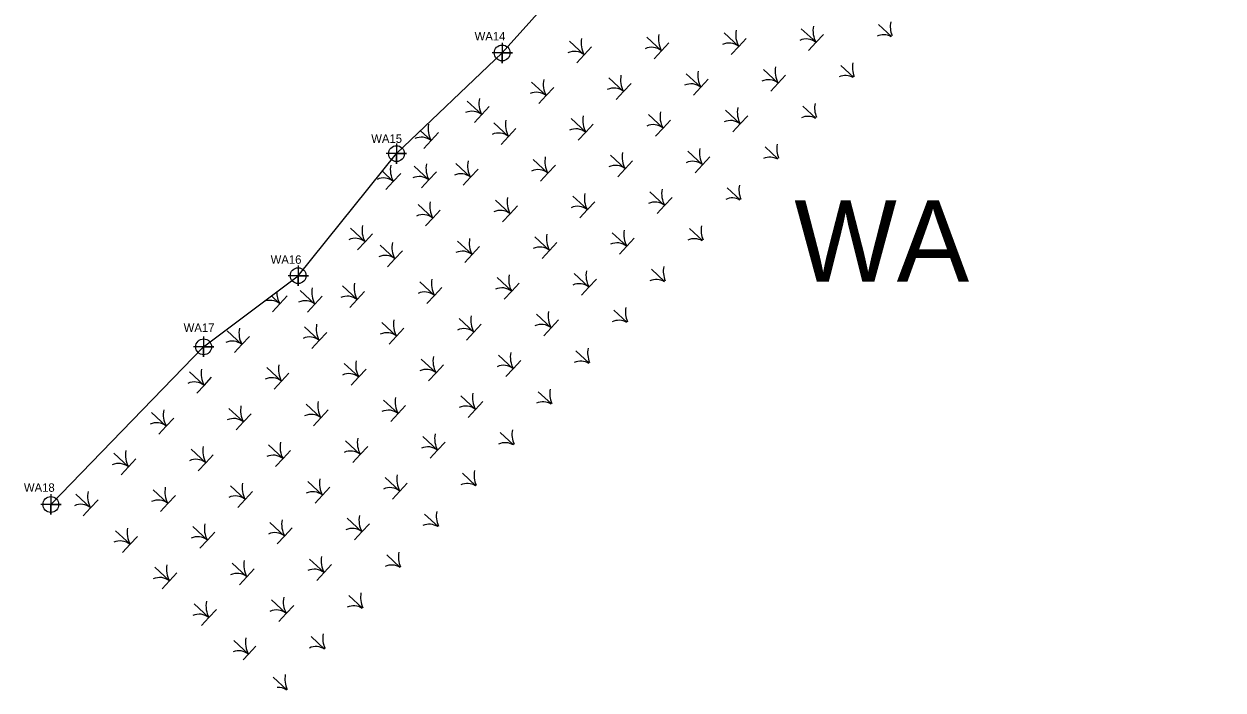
# Model space of a CAD drawing. Extents: x 2130226 to 2130625, y 149525 to 150037.
# Drawn here: x 2130259.3 to 2130613.9, y 149524.5 to 149721.4 of the extents above; entities that cross this region are included whole.
import ezdxf

# ---------------------------------------------------------------- set-up
doc = ezdxf.new("R2010")
doc.units = 0
for name, color, linetype in [('Default', 7, 'Continuous'), ('Exist Environmental Wetland Boundary', 7, 'Continuous'), ('Exist Environmental Wetland Boundary Cogo Number', 7, 'Continuous'), ('Exist Environmental Wetland Boundary Cogo Point CELL', 7, 'Continuous')]:
    doc.layers.add(name, color=color, linetype=linetype)

msp = doc.modelspace()

# ---------------------------------------------------------------- linework, layer by layer
at = {"layer": 'Exist Environmental Wetland Boundary'}
msp.add_lwpolyline([(2130267.29, 149579.38), (2130312.46, 149626), (2130340.44, 149647.02), (2130369.49, 149683.11), (2130400.77, 149712.88), (2130426.19, 149741.24), (2130464.98, 149782.24), (2130485.26, 149806.46), (2130501.4, 149821.48), (2130516.1, 149818.66), (2130536.83, 149803.31), (2130542.55, 149811.9), (2130506.33, 149839.82), (2130501.18, 149853.93), (2130523.76, 149857.7), (2130544.93, 149871.63), (2130588.13, 149840.59), (2130613.94, 149823.8)], dxfattribs=at)
at = {"layer": 'Exist Environmental Wetland Boundary Cogo Point CELL'}
for points in [[(2130515.85, 149717.78), (2130512.09, 149721.26), (2130515.85, 149717.78)], [(2130445.66, 149711.18), (2130447.85, 149713.54), (2130443.51, 149717.57), (2130447.85, 149713.54), (2130450.05, 149715.91)], [(2130468.52, 149712.41), (2130470.71, 149714.77), (2130466.37, 149718.8), (2130470.71, 149714.77), (2130472.9, 149717.14)], [(2130491.37, 149713.64), (2130493.57, 149716.01), (2130489.23, 149720.03), (2130493.57, 149716.01), (2130495.76, 149718.37)], [(2130400.77, 149715.88), (2130400.77, 149709.88), (2130400.77, 149712.88), (2130403.77, 149712.88), (2130397.77, 149712.88)], [(2130422.8, 149709.94), (2130424.99, 149712.31), (2130420.66, 149716.33), (2130424.99, 149712.31), (2130427.19, 149714.67)], [(2130457.33, 149700.35), (2130459.52, 149702.71), (2130455.18, 149706.74), (2130459.52, 149702.71), (2130461.71, 149705.08)], [(2130480.18, 149701.58), (2130482.38, 149703.95), (2130478.04, 149707.97), (2130482.38, 149703.95), (2130484.57, 149706.31)], [(2130504.67, 149705.7), (2130500.9, 149709.2), (2130504.67, 149705.7)], [(2130411.61, 149697.88), (2130413.8, 149700.25), (2130409.47, 149704.27), (2130413.8, 149700.25), (2130416, 149702.61)], [(2130434.47, 149699.12), (2130436.66, 149701.48), (2130432.32, 149705.51), (2130436.66, 149701.48), (2130438.86, 149703.85)], [(2130392.57, 149692.26), (2130394.77, 149694.63), (2130390.43, 149698.65), (2130394.77, 149694.63), (2130396.96, 149696.99)], [(2130468.99, 149689.52), (2130471.19, 149691.89), (2130466.85, 149695.91), (2130471.19, 149691.89), (2130473.38, 149694.25)], [(2130493.5, 149693.63), (2130489.71, 149697.14), (2130493.5, 149693.63)], [(2130400.42, 149685.83), (2130402.61, 149688.19), (2130398.28, 149692.22), (2130402.61, 149688.19), (2130404.81, 149690.55)], [(2130423.28, 149687.06), (2130425.47, 149689.42), (2130421.13, 149693.45), (2130425.47, 149689.42), (2130427.67, 149691.79)], [(2130446.14, 149688.29), (2130448.33, 149690.65), (2130443.99, 149694.68), (2130448.33, 149690.65), (2130450.52, 149693.02)], [(2130377.56, 149684.59), (2130379.76, 149686.96), (2130376.61, 149689.88)], [(2130376.61, 149689.88), (2130379.76, 149686.96), (2130381.95, 149689.32)], [(2130369.49, 149686.11), (2130369.49, 149680.11), (2130369.49, 149683.11), (2130372.49, 149683.11), (2130366.49, 149683.11)], [(2130482.33, 149681.55), (2130478.52, 149685.08), (2130482.33, 149681.55)], [(2130412.09, 149675), (2130414.28, 149677.36), (2130409.94, 149681.39), (2130414.28, 149677.36), (2130416.48, 149679.73)], [(2130434.95, 149676.23), (2130437.14, 149678.6), (2130432.8, 149682.62), (2130437.14, 149678.6), (2130439.33, 149680.96)], [(2130457.8, 149677.46), (2130460, 149679.83), (2130455.66, 149683.85), (2130460, 149679.83), (2130462.19, 149682.19)], [(2130366.37, 149672.53), (2130368.57, 149674.9), (2130365.32, 149677.91)], [(2130365.32, 149677.91), (2130368.57, 149674.9), (2130370.76, 149677.26)], [(2130376.92, 149672.96), (2130379.11, 149675.32), (2130374.78, 149679.35), (2130379.11, 149675.32), (2130381.31, 149677.69)], [(2130389.23, 149673.77), (2130391.42, 149676.13), (2130387.09, 149680.16), (2130391.42, 149676.13), (2130393.62, 149678.5)], [(2130423.76, 149664.17), (2130425.95, 149666.54), (2130421.61, 149670.56), (2130425.95, 149666.54), (2130428.14, 149668.9)], [(2130446.61, 149665.4), (2130448.81, 149667.77), (2130444.47, 149671.79), (2130448.81, 149667.77), (2130451, 149670.13)], [(2130471.16, 149669.47), (2130467.33, 149673.03), (2130471.16, 149669.47)], [(2130378.04, 149661.71), (2130380.23, 149664.07), (2130375.9, 149668.1), (2130380.23, 149664.07), (2130382.43, 149666.44)], [(2130400.9, 149662.94), (2130403.09, 149665.3), (2130398.75, 149669.33), (2130403.09, 149665.3), (2130405.29, 149667.67)], [(2130358.01, 149654.71), (2130360.2, 149657.07), (2130355.87, 149661.1), (2130360.2, 149657.07), (2130362.4, 149659.44)], [(2130459.98, 149657.4), (2130456.14, 149660.97), (2130459.98, 149657.4)], [(2130389.71, 149650.88), (2130391.9, 149653.24), (2130387.56, 149657.27), (2130391.9, 149653.24), (2130394.1, 149655.61)], [(2130412.57, 149652.11), (2130414.76, 149654.48), (2130410.42, 149658.5), (2130414.76, 149654.48), (2130416.95, 149656.84)], [(2130435.42, 149653.34), (2130437.62, 149655.71), (2130433.28, 149659.73), (2130437.62, 149655.71), (2130439.81, 149658.07)], [(2130366.85, 149649.65), (2130369.04, 149652.01), (2130364.71, 149656.04), (2130369.04, 149652.01), (2130371.24, 149654.38)], [(2130340.44, 149650.02), (2130340.44, 149644.02), (2130340.44, 149647.02), (2130343.44, 149647.02), (2130337.44, 149647.02)], [(2130401.38, 149640.05), (2130403.57, 149642.42), (2130399.23, 149646.44), (2130403.57, 149642.42), (2130405.76, 149644.78)], [(2130424.23, 149641.28), (2130426.43, 149643.65), (2130422.09, 149647.67), (2130426.43, 149643.65), (2130428.62, 149646.01)], [(2130448.81, 149645.32), (2130444.95, 149648.91), (2130448.81, 149645.32)], [(2130343.18, 149636.25), (2130345.37, 149638.61), (2130341.03, 149642.64), (2130345.37, 149638.61), (2130347.56, 149640.98)], [(2130355.66, 149637.59), (2130357.85, 149639.95), (2130353.52, 149643.98), (2130357.85, 149639.95), (2130360.05, 149642.32)], [(2130378.52, 149638.82), (2130380.71, 149641.19), (2130376.37, 149645.21), (2130380.71, 149641.19), (2130382.91, 149643.55)], [(2130332.49, 149641.04), (2130335, 149638.72), (2130337.19, 149641.09)], [(2130332.8, 149636.36), (2130335, 149638.72), (2130332.49, 149641.04)], [(2130413.04, 149629.23), (2130415.24, 149631.59), (2130410.9, 149635.62), (2130415.24, 149631.59), (2130417.43, 149633.95)], [(2130437.64, 149633.25), (2130433.76, 149636.85), (2130437.64, 149633.25)], [(2130344.47, 149625.53), (2130346.66, 149627.89), (2130342.33, 149631.92), (2130346.66, 149627.89), (2130348.86, 149630.26)], [(2130367.33, 149626.76), (2130369.52, 149629.13), (2130365.18, 149633.15), (2130369.52, 149629.13), (2130371.72, 149631.49)], [(2130390.19, 149627.99), (2130392.38, 149630.36), (2130388.04, 149634.38), (2130392.38, 149630.36), (2130394.57, 149632.72)], [(2130312.46, 149629), (2130312.46, 149623), (2130312.46, 149626), (2130315.46, 149626), (2130309.46, 149626)], [(2130321.61, 149624.3), (2130323.81, 149626.66), (2130319.47, 149630.69), (2130323.81, 149626.66), (2130326, 149629.03)], [(2130426.47, 149621.17), (2130422.57, 149624.79), (2130426.47, 149621.17)], [(2130356.14, 149614.7), (2130358.33, 149617.07), (2130353.99, 149621.09), (2130358.33, 149617.07), (2130360.53, 149619.43)], [(2130379, 149615.93), (2130381.19, 149618.3), (2130376.85, 149622.32), (2130381.19, 149618.3), (2130383.38, 149620.66)], [(2130401.85, 149617.17), (2130404.05, 149619.53), (2130399.71, 149623.56), (2130404.05, 149619.53), (2130406.24, 149621.9)], [(2130310.42, 149612.24), (2130312.62, 149614.6), (2130308.28, 149618.63), (2130312.62, 149614.6), (2130314.81, 149616.97)], [(2130333.28, 149613.47), (2130335.47, 149615.83), (2130331.14, 149619.86), (2130335.47, 149615.83), (2130337.67, 149618.2)], [(2130367.81, 149603.87), (2130370, 149606.24), (2130365.66, 149610.26), (2130370, 149606.24), (2130372.19, 149608.6)], [(2130390.66, 149605.11), (2130392.86, 149607.47), (2130388.52, 149611.5), (2130392.86, 149607.47), (2130395.05, 149609.84)], [(2130415.3, 149609.09), (2130411.38, 149612.73), (2130415.3, 149609.09)], [(2130322.09, 149601.41), (2130324.28, 149603.77), (2130319.95, 149607.8), (2130324.28, 149603.77), (2130326.48, 149606.14)], [(2130344.95, 149602.64), (2130347.14, 149605.01), (2130342.8, 149609.03), (2130347.14, 149605.01), (2130349.34, 149607.37)], [(2130299.23, 149600.18), (2130301.43, 149602.54), (2130297.09, 149606.57), (2130301.43, 149602.54), (2130303.62, 149604.91)], [(2130404.12, 149597.02), (2130400.19, 149600.67), (2130404.12, 149597.02)], [(2130333.76, 149590.58), (2130335.95, 149592.95), (2130331.61, 149596.97), (2130335.95, 149592.95), (2130338.15, 149595.31)], [(2130356.62, 149591.82), (2130358.81, 149594.18), (2130354.47, 149598.21), (2130358.81, 149594.18), (2130361, 149596.54)], [(2130379.47, 149593.05), (2130381.67, 149595.41), (2130377.33, 149599.44), (2130381.67, 149595.41), (2130383.86, 149597.78)], [(2130288.04, 149588.12), (2130290.24, 149590.48), (2130285.9, 149594.51), (2130290.24, 149590.48), (2130292.43, 149592.85)], [(2130310.9, 149589.35), (2130313.09, 149591.72), (2130308.76, 149595.74), (2130313.09, 149591.72), (2130315.29, 149594.08)], [(2130345.43, 149579.76), (2130347.62, 149582.12), (2130343.28, 149586.15), (2130347.62, 149582.12), (2130349.81, 149584.49)], [(2130368.28, 149580.99), (2130370.48, 149583.35), (2130366.14, 149587.38), (2130370.48, 149583.35), (2130372.67, 149585.72)], [(2130392.95, 149584.94), (2130389, 149588.61), (2130392.95, 149584.94)], [(2130267.29, 149582.38), (2130267.29, 149576.38), (2130267.29, 149579.38), (2130270.29, 149579.38), (2130264.29, 149579.38)], [(2130276.85, 149576.06), (2130279.05, 149578.42), (2130274.71, 149582.45), (2130279.05, 149578.42), (2130281.24, 149580.79)], [(2130299.71, 149577.29), (2130301.9, 149579.66), (2130297.57, 149583.68), (2130301.9, 149579.66), (2130304.1, 149582.02)], [(2130322.57, 149578.52), (2130324.76, 149580.89), (2130320.42, 149584.91), (2130324.76, 149580.89), (2130326.96, 149583.25)], [(2130357.09, 149568.93), (2130359.29, 149571.29), (2130354.95, 149575.32), (2130359.29, 149571.29), (2130361.48, 149573.66)], [(2130381.78, 149572.87), (2130377.81, 149576.55), (2130381.78, 149572.87)], [(2130288.52, 149565.23), (2130290.71, 149567.6), (2130286.38, 149571.62), (2130290.71, 149567.6), (2130292.91, 149569.96)], [(2130311.38, 149566.46), (2130313.57, 149568.83), (2130309.23, 149572.85), (2130313.57, 149568.83), (2130315.77, 149571.19)], [(2130334.24, 149567.7), (2130336.43, 149570.06), (2130332.09, 149574.09), (2130336.43, 149570.06), (2130338.62, 149572.43)], [(2130370.61, 149560.79), (2130366.62, 149564.49), (2130370.61, 149560.79)], [(2130300.19, 149554.41), (2130302.38, 149556.77), (2130298.04, 149560.8), (2130302.38, 149556.77), (2130304.58, 149559.13)], [(2130323.05, 149555.64), (2130325.24, 149558), (2130320.9, 149562.03), (2130325.24, 149558), (2130327.43, 149560.37)], [(2130345.9, 149556.87), (2130348.1, 149559.23), (2130343.76, 149563.26), (2130348.1, 149559.23), (2130350.29, 149561.6)], [(2130311.86, 149543.58), (2130314.05, 149545.94), (2130309.71, 149549.97), (2130314.05, 149545.94), (2130316.24, 149548.31)], [(2130334.71, 149544.81), (2130336.91, 149547.18), (2130332.57, 149551.2), (2130336.91, 149547.18), (2130339.1, 149549.54)], [(2130359.43, 149548.72), (2130355.43, 149552.43), (2130359.43, 149548.72)], [(2130348.26, 149536.64), (2130344.24, 149540.37), (2130348.26, 149536.64)], [(2130324.15, 149533.43), (2130325.72, 149535.12), (2130321.38, 149539.14), (2130325.72, 149535.12), (2130327.91, 149537.48)], [(2130337.09, 149524.56), (2130333.05, 149528.31), (2130337.09, 149524.56)]]:
    msp.add_lwpolyline(points, dxfattribs=at)
for centre in [(2130400.77, 149712.88), (2130369.49, 149683.11), (2130340.44, 149647.02), (2130312.46, 149626), (2130267.29, 149579.38)]:
    msp.add_circle(centre, 2.34, dxfattribs=at)
for centre, radius, start, end in [((2130499.89, 149719.47), 7.21, 169.2688, 208.7635), ((2130522.75, 149720.71), 7.21, 169.2688, 201.9706), ((2130431.31, 149715.78), 7.21, 169.2688, 208.7635), ((2130454.17, 149717.01), 7.21, 169.2688, 208.7635), ((2130477.03, 149718.24), 7.21, 169.2688, 208.7635), ((2130490.68, 149712.41), 4.61, 51.2816, 114.6763), ((2130513.54, 149713.64), 4.61, 61.2666, 114.6763), ((2130422.11, 149708.71), 4.61, 51.2816, 114.6763), ((2130444.97, 149709.94), 4.61, 51.2816, 114.6763), ((2130467.83, 149711.17), 4.61, 51.2816, 114.6763), ((2130511.56, 149708.65), 7.21, 169.2688, 202.1834), ((2130442.98, 149704.95), 7.21, 169.2688, 208.7635), ((2130465.84, 149706.18), 7.21, 169.2688, 208.7635), ((2130488.7, 149707.41), 7.21, 169.2688, 208.7635), ((2130502.35, 149701.58), 4.61, 60.9566, 114.6763), ((2130420.12, 149703.72), 7.21, 169.2688, 208.7635), ((2130433.78, 149697.88), 4.61, 51.2816, 114.6763), ((2130456.64, 149699.12), 4.61, 51.2816, 114.6763), ((2130479.49, 149700.35), 4.61, 51.2816, 114.6763), ((2130401.09, 149698.09), 7.21, 169.2688, 208.7635), ((2130410.92, 149696.65), 4.61, 51.2816, 114.6763), ((2130391.88, 149691.03), 4.61, 51.2816, 114.6763), ((2130454.65, 149694.12), 7.21, 169.2688, 208.7635), ((2130477.51, 149695.36), 7.21, 169.2688, 208.7635), ((2130500.37, 149696.59), 7.21, 169.2688, 202.3958), ((2130386.07, 149690.43), 7.21, 169.2688, 208.7635), ((2130408.93, 149691.66), 7.21, 169.2688, 208.7635), ((2130431.79, 149692.89), 7.21, 169.2688, 208.7635), ((2130468.3, 149688.29), 4.61, 51.2816, 114.6763), ((2130491.16, 149689.52), 4.61, 60.6469, 114.6763), ((2130399.73, 149684.59), 4.61, 51.2816, 114.6763), ((2130422.59, 149685.82), 4.61, 51.2816, 114.6763), ((2130445.45, 149687.06), 4.61, 51.2816, 114.6763), ((2130376.87, 149683.36), 4.61, 51.2816, 114.6763), ((2130466.32, 149683.3), 7.21, 169.2688, 208.7635), ((2130489.18, 149684.53), 7.21, 169.2688, 202.6078), ((2130420.6, 149680.83), 7.21, 169.2688, 208.7635), ((2130443.46, 149682.06), 7.21, 169.2688, 208.7635), ((2130479.97, 149677.46), 4.61, 60.3376, 114.6763), ((2130374.88, 149678.37), 7.21, 169.2688, 208.7635), ((2130385.43, 149678.79), 7.21, 169.2688, 208.7635), ((2130397.74, 149679.6), 7.21, 169.2688, 208.7635), ((2130411.4, 149673.76), 4.61, 51.2816, 114.6763), ((2130434.26, 149675), 4.61, 51.2816, 114.6763), ((2130457.11, 149676.23), 4.61, 51.2816, 114.6763), ((2130365.68, 149671.3), 4.61, 51.2816, 114.6763), ((2130376.23, 149671.73), 4.61, 51.2816, 114.6763), ((2130388.54, 149672.53), 4.61, 51.2816, 114.6763), ((2130432.27, 149670), 7.21, 169.2688, 208.7635), ((2130455.13, 149671.24), 7.21, 169.2688, 208.7635), ((2130477.99, 149672.47), 7.21, 169.2688, 202.8195), ((2130386.55, 149667.54), 7.21, 169.2688, 208.7635), ((2130409.41, 149668.77), 7.21, 169.2688, 208.7635), ((2130423.07, 149662.94), 4.61, 51.2816, 114.6763), ((2130445.92, 149664.17), 4.61, 51.2816, 114.6763), ((2130468.78, 149665.4), 4.61, 60.0287, 114.6763), ((2130377.35, 149660.47), 4.61, 51.2816, 114.6763), ((2130400.21, 149661.71), 4.61, 51.2816, 114.6763), ((2130366.52, 149660.54), 7.21, 169.2688, 208.7635), ((2130443.94, 149659.18), 7.21, 169.2688, 208.7635), ((2130466.8, 149660.41), 7.21, 169.2688, 203.0308), ((2130357.32, 149653.47), 4.61, 51.2816, 114.6763), ((2130375.36, 149655.48), 7.21, 169.2688, 208.7635), ((2130398.22, 149656.71), 7.21, 169.2688, 208.7635), ((2130421.08, 149657.95), 7.21, 169.2688, 208.7635), ((2130434.73, 149652.11), 4.61, 51.2816, 114.6763), ((2130457.59, 149653.34), 4.61, 59.7202, 114.6763), ((2130366.16, 149648.41), 4.61, 51.2816, 114.6763), ((2130389.02, 149649.65), 4.61, 51.2816, 114.6763), ((2130411.88, 149650.88), 4.61, 51.2816, 114.6763), ((2130455.61, 149648.35), 7.21, 169.2688, 203.2417), ((2130387.03, 149644.65), 7.21, 169.2688, 208.7635), ((2130409.89, 149645.89), 7.21, 169.2688, 208.7635), ((2130432.75, 149647.12), 7.21, 169.2688, 208.7635), ((2130446.4, 149641.28), 4.61, 59.4121, 114.6763), ((2130341.31, 149642.19), 7.21, 179.4775, 208.7635), ((2130351.69, 149642.08), 7.21, 169.2688, 208.7635), ((2130364.17, 149643.42), 7.21, 169.2688, 208.7635), ((2130377.83, 149637.59), 4.61, 51.2816, 114.6763), ((2130400.69, 149638.82), 4.61, 51.2816, 114.6763), ((2130423.54, 149640.05), 4.61, 51.2816, 114.6763), ((2130332.11, 149635.12), 4.61, 51.2816, 114.548), ((2130342.49, 149635.01), 4.61, 51.2816, 114.6763), ((2130354.97, 149636.35), 4.61, 51.2816, 114.6763), ((2130398.7, 149633.83), 7.21, 169.2688, 208.7635), ((2130421.56, 149635.06), 7.21, 169.2688, 208.7635), ((2130444.42, 149636.29), 7.21, 169.2688, 203.4523), ((2130330.12, 149630.13), 7.21, 169.2688, 208.7635), ((2130352.98, 149631.36), 7.21, 169.2688, 208.7635), ((2130375.84, 149632.59), 7.21, 169.2688, 208.7635), ((2130412.35, 149627.99), 4.61, 51.2816, 114.6763), ((2130435.21, 149629.22), 4.61, 59.1043, 114.6763), ((2130343.78, 149624.3), 4.61, 51.2816, 114.6763), ((2130366.64, 149625.53), 4.61, 51.2816, 114.6763), ((2130389.5, 149626.76), 4.61, 51.2816, 114.6763), ((2130320.92, 149623.06), 4.61, 51.2816, 114.6763), ((2130410.37, 149623), 7.21, 169.2688, 208.7635), ((2130433.23, 149624.23), 7.21, 169.2688, 203.6626), ((2130364.65, 149620.54), 7.21, 169.2688, 208.7635), ((2130387.51, 149621.77), 7.21, 169.2688, 208.7635), ((2130424.02, 149617.16), 4.61, 58.7969, 114.6763), ((2130318.93, 149618.07), 7.21, 169.2688, 208.7635), ((2130341.79, 149619.3), 7.21, 169.2688, 208.7635), ((2130355.45, 149613.47), 4.61, 51.2816, 114.6763), ((2130378.31, 149614.7), 4.61, 51.2816, 114.6763), ((2130401.16, 149615.93), 4.61, 51.2816, 114.6763), ((2130309.73, 149611), 4.61, 51.2816, 114.6763), ((2130332.59, 149612.24), 4.61, 51.2816, 114.6763), ((2130376.32, 149609.71), 7.21, 169.2688, 208.7635), ((2130399.18, 149610.94), 7.21, 169.2688, 208.7635), ((2130422.04, 149612.17), 7.21, 169.2688, 203.8726), ((2130307.74, 149606.01), 7.21, 169.2688, 208.7635), ((2130330.6, 149607.24), 7.21, 169.2688, 208.7635), ((2130353.46, 149608.48), 7.21, 169.2688, 208.7635), ((2130367.12, 149602.64), 4.61, 51.2816, 114.6763), ((2130389.97, 149603.87), 4.61, 51.2816, 114.6763), ((2130412.83, 149605.11), 4.61, 58.4898, 114.6763), ((2130298.54, 149598.94), 4.61, 51.2816, 114.6763), ((2130321.4, 149600.18), 4.61, 51.2816, 114.6763), ((2130344.26, 149601.41), 4.61, 51.2816, 114.6763), ((2130387.99, 149598.88), 7.21, 169.2688, 208.7635), ((2130410.85, 149600.11), 7.21, 169.2688, 204.0822), ((2130319.41, 149595.18), 7.21, 169.2688, 208.7635), ((2130342.27, 149596.42), 7.21, 169.2688, 208.7635), ((2130365.13, 149597.65), 7.21, 169.2688, 208.7635), ((2130378.78, 149591.81), 4.61, 51.2816, 114.6763), ((2130401.64, 149593.05), 4.61, 58.183, 114.6763), ((2130296.55, 149593.95), 7.21, 169.2688, 208.7635), ((2130310.21, 149588.12), 4.61, 51.2816, 114.6763), ((2130333.07, 149589.35), 4.61, 51.2816, 114.6763), ((2130355.93, 149590.58), 4.61, 51.2816, 114.6763), ((2130287.35, 149586.89), 4.61, 51.2816, 114.6763), ((2130399.66, 149588.05), 7.21, 169.2688, 204.2914), ((2130331.08, 149584.36), 7.21, 169.2688, 208.7635), ((2130353.94, 149585.59), 7.21, 169.2688, 208.7635), ((2130376.8, 149586.82), 7.21, 169.2688, 208.7635), ((2130390.45, 149580.99), 4.61, 57.8766, 114.6763), ((2130285.36, 149581.89), 7.21, 169.2688, 208.7635), ((2130308.22, 149583.13), 7.21, 169.2688, 208.7635), ((2130321.88, 149577.29), 4.61, 51.2816, 114.6763), ((2130344.74, 149578.52), 4.61, 51.2816, 114.6763), ((2130367.59, 149579.75), 4.61, 51.2816, 114.6763), ((2130276.16, 149574.83), 4.61, 51.2816, 114.6763), ((2130299.02, 149576.06), 4.61, 51.2816, 114.6763), ((2130342.75, 149573.53), 7.21, 169.2688, 208.7635), ((2130365.61, 149574.76), 7.21, 169.2688, 208.7635), ((2130388.47, 149575.99), 7.21, 169.2688, 204.5004), ((2130297.03, 149571.07), 7.21, 169.2688, 208.7635), ((2130319.89, 149572.3), 7.21, 169.2688, 208.7635), ((2130356.4, 149567.7), 4.61, 51.2816, 114.6763), ((2130379.26, 149568.93), 4.61, 57.5704, 114.6763), ((2130287.83, 149564), 4.61, 51.2816, 114.6763), ((2130310.69, 149565.23), 4.61, 51.2816, 114.6763), ((2130333.55, 149566.46), 4.61, 51.2816, 114.6763), ((2130354.42, 149562.7), 7.21, 169.2688, 208.7635), ((2130377.28, 149563.94), 7.21, 169.2688, 204.709), ((2130308.7, 149560.24), 7.21, 169.2688, 208.7635), ((2130331.56, 149561.47), 7.21, 169.2688, 208.7635), ((2130368.07, 149556.87), 4.61, 57.2646, 114.6763), ((2130299.5, 149553.17), 4.61, 51.2816, 114.6763), ((2130322.36, 149554.4), 4.61, 51.2816, 114.6763), ((2130345.21, 149555.64), 4.61, 51.2816, 114.6763), ((2130320.37, 149549.41), 7.21, 169.2688, 208.7635), ((2130343.23, 149550.64), 7.21, 169.2688, 208.7635), ((2130366.09, 149551.88), 7.21, 169.2688, 204.9174), ((2130311.17, 149542.34), 4.61, 51.2816, 114.6763), ((2130334.02, 149543.58), 4.61, 51.2816, 114.6763), ((2130356.88, 149544.81), 4.61, 56.959, 114.6763), ((2130332.04, 149538.58), 7.21, 169.2688, 208.7635), ((2130354.9, 149539.82), 7.21, 169.2688, 205.1254), ((2130322.83, 149531.52), 4.61, 51.2816, 110.8721), ((2130345.69, 149532.75), 4.61, 56.6538, 114.6763), ((2130343.71, 149527.76), 7.21, 169.2688, 205.3331), ((2130334.5, 149520.69), 4.61, 56.3488, 93.4478)]:
    msp.add_arc(centre, radius, start, end, dxfattribs=at)

# ---------------------------------------------------------------- texts
at = {"layer": 'Default'}
msp.add_text('WA', height=24, dxfattribs=at).set_placement((2130487.16, 149645.28))
at = {"layer": 'Exist Environmental Wetland Boundary Cogo Number'}
for s, p in [('WA14', (2130392.61, 149716.57)), ('WA15', (2130362.04, 149686.29)), ('WA16', (2130332.29, 149650.54)), ('WA17', (2130306.56, 149630.39)), ('WA18', (2130259.32, 149583.13))]:
    msp.add_text(s, height=2.5, dxfattribs=at).set_placement(p)

doc.saveas('drawing.dxf')
